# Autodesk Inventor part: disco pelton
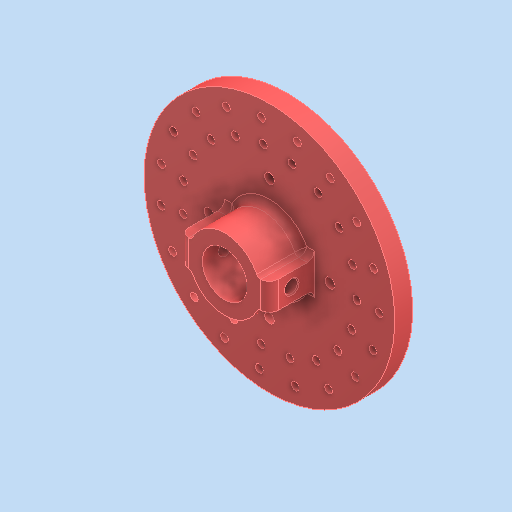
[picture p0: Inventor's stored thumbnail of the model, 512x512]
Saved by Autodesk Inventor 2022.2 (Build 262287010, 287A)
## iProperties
Created: 2025-03
Part Number: disco pelton
Material: Plastica ABS
Document SubType Name: Modeling
Designer: 18907419
Density: 1.06 g/cm^3
Appearance: Default
Author: 18907419
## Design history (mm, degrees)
feature "Solido1"
node "Solido2"
